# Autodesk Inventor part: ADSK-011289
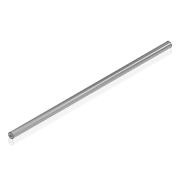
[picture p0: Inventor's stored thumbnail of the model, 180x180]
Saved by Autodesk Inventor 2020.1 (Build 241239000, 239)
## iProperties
Created: 1999-11
Part Number: ADSK-011289
Description: SHFTTA,RT,AX,375,12,FF
Document SubType Name: Modeling
Designer: sspink
Material: Générique
Density: 1 g/cm^3
Appearance: Chrom - poliert
Mass: 761.121 g
Surface Area: 992.965 cm^2
Volume: 761.121 cm^3
Control State: 0
Checked Out: False
Last Check In By: sspink
Last Check In Date: 1999-12-22
Master: False
Shininess: 0.0
Length Units: 11269
Angle Units: 11279
Time Units: 11290
Mass Units: 11283
Length Display Precision: 3
Angle Display Precision: 2
Compacted: True
Dimensions: 32x32x953,5 mm
Mass: 0,761 kg
DocNumber: ADSK-011289.ipt
Folder: 01 - Themengebiete\Simplification\01 - Packaging machine\
VDS_Category: 3D Komponenten
Density: 0.0
Volumn: 0.0
Area: 0.0
PropertySet Name: Model Information
Author: sspink
Revision Number: -
Title: SHFTTA,RT,AX,375,12,FF
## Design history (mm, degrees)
node "Solide1"
  node "Extrusion1" dims "d1" = 953.5, "d2" = 0
  node "Hole1" dims "d3" = 10.106, "d4" = 9.525, "d5" = 6.35, "d6" = 60 deg, "d7" = 32.3, "d8" = 118 deg, "d15" = 24
  node "Hole2" dims "d9" = 10.106, "d10" = 9.525, "d11" = 6.35, "d12" = 60 deg, "d13" = 32.3, "d14" = 118 deg, "d16" = 24
sketch "Sketch1"
  geometry: C1 r 16 at (0, 0)
  constraints: 1 centre point
  dimensions: "d0" = 32 diameter of C1
chamfer "Fase1" distance "d17" = 2; stored, may be unused: second distance "d18" = 2, angle "d19" = 45 deg
node "Corps solides"
node "Corps surfaciques"
sketch "Sketch2"
  geometry: C1 r 16 at (0, 0) reference; 1 further point
  constraints: 1 coincident
sketch "Sketch4"
  geometry: C1 r 16 at (0, 0) reference; 1 further point
  constraints: 1 coincident
